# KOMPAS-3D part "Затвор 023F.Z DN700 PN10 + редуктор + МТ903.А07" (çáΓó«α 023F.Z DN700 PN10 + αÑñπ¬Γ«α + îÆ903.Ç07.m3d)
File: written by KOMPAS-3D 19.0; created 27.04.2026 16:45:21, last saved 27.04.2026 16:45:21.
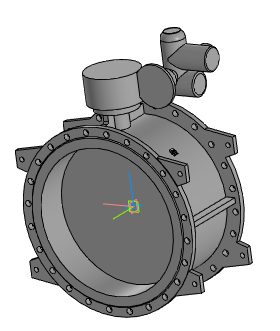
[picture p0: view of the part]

Document properties: Полное имя файла: ..\..\Затвор 023F.Z DN400-DN1600 + редуктор + МТ903\Затвор 023F.Z DN700 PN10 + редуктор + МТ903.А07.a3d

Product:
- Part/product: Затвор 023F.Z DN700 PN10 + редуктор + МТ903.А07
    Масса: 625.316

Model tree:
1. Операция без истории:1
